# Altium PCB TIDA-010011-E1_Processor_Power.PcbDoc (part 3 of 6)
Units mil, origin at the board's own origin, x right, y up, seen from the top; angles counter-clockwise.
Board outline 4921.26 x 4921.26 mil, 4 copper layers (Top Layer, Gnd layer, Gnd/Pwr layer, Bottom Layer), stack 62.634 mil thick; 631 components, 254 nets, 1751 pads, 757 vias.
Unrouted connection lines stored in the file: 1.
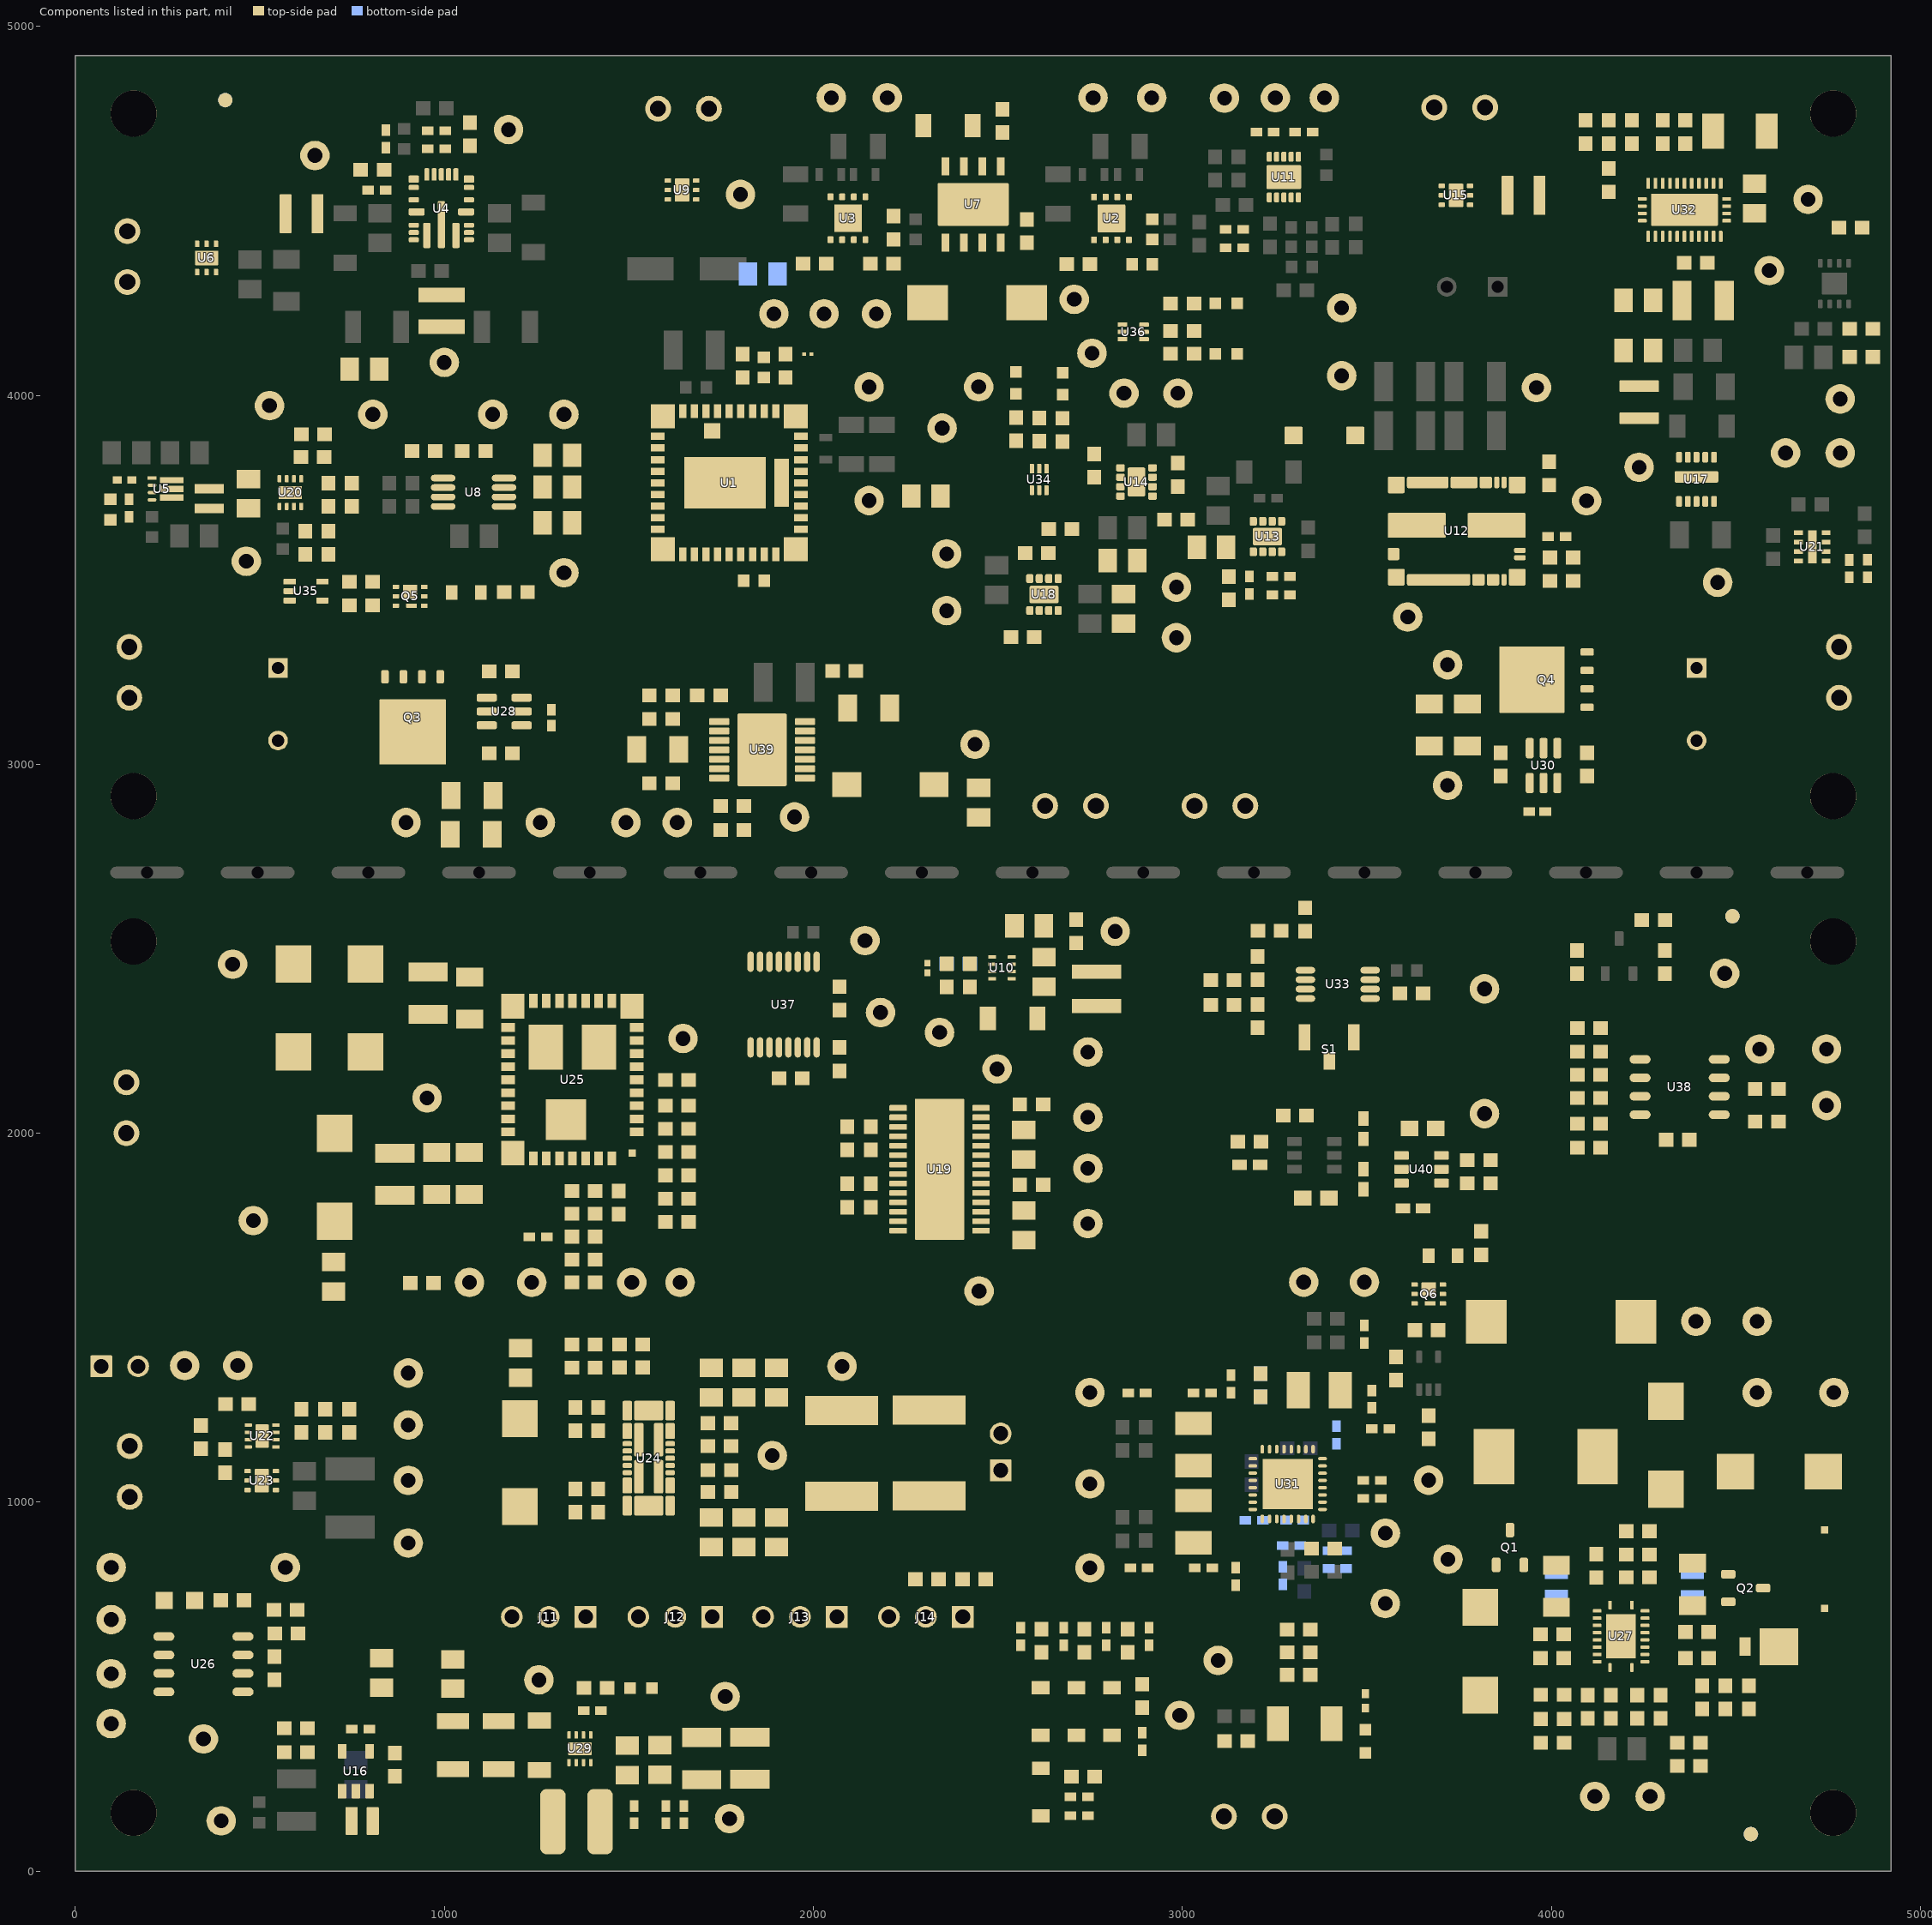
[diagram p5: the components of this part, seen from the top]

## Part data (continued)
C67 C148: "CAP, CERM, 0.1 µF, 25 V,+/- 10%, X7R, 0603", Cap_Case=0603, Manufacturer=MuRata, Supplier Part Number 1=490-1524-1-ND, TempCo=X7R, Tolerance_%=10, Value2=25V, ValueDisplayed=0.1µF
C68 C109 C123: "CAP, CERM, 0.01 µF, 25 V,+/- 10%, X7R, 0603", Cap_Case=0603, Manufacturer=MuRata, Supplier Part Number 1=490-1520-1-ND, TempCo=X7R, Tolerance_%=10, Value2=25V, ValueDisplayed=0.01µF
C69: "CAP, TA, 100 µF, 20 V, +/- 10%, 0.5 ohm, SMD", Cap_Case=E, Manufacturer=Vishay-Sprague, Supplier Part Number 1=718-1024-1-ND, Tolerance_%=10, Value1="0.5 ohm", Value2=20V, ValueDisplayed=100µF
C72 C76 C77 C79 C83 C85 C86: "CAP, CERM, 1 µF, 16 V,+/- 10%, X7R, 0603", Cap_Case=0603, Manufacturer=TDK, Supplier Part Number 1=445-1604-1-ND, TempCo=X7R, Tolerance_%=10, Value1="0.0057 ohm", Value2=16V, ValueDisplayed=1µF
C88 C89 C90 C91: "CAP, CERM, 22 µF, 10 V,+/- 20%, X5R, 0603", Cap_Case=0603, Manufacturer=MuRata, Supplier Part Number 1=490-10476-1-ND, TempCo=X5R, Tolerance_%=20, Value2=10V, ValueDisplayed=22µF
C92 C93 C94 C95 C96 C97 C163: "CAP, CERM, 22 µF, 25 V,+/- 20%, X5R, 0805", Cap_Case=0805, Manufacturer=MuRata, Supplier Part Number 1=490-10749-1-ND, TempCo=X5R, Tolerance_%=20, Value2=25V, ValueDisplayed=22µF
C98 C99: "CAP, CERM, 47 µF, 25 V,+/- 20%, X7S, 6x5x5mm", Cap_Case=2220, Manufacturer=TDK, Supplier Part Number 1=445-7106-1-ND, TempCo=X7S, Tolerance_%=20, Value2=25V, ValueDisplayed=47µF
C100: "CAP, CERM, 3300 pF, 50 V,+/- 10%, X7R, 0603", Cap_Case=0603, Manufacturer=MuRata, Supplier Part Number 1=490-1503-1-ND, TempCo=X7R, Tolerance_%=10, Value2=50V, ValueDisplayed=3300pF
C101 C105: "CAP, Tantalum Polymer, 220 µF, 10 V,+/- 20%, 0.025 ohm, 7343-30 SMD", Cap_Case=7343-30, Manufacturer=Panasonic, Supplier Part Number 1=P16451CT-ND, Tolerance_%=20, Value1="0.025 ohm", Value2=10V, ValueDisplayed=220µF
C102 C103 C108 C162 C164: "CAP, CERM, 0.1 µF, 50 V,+/- 5%, X7R, 1206", Cap_Case=1206, Manufacturer=Kemet, Supplier Part Number 1=399-1250-1-ND, TempCo=X7R, Tolerance_%=5, Value1="0.059 ohm", Value2=50V, ValueDisplayed=0.1µF
C104: "CAP, CERM, 47 µF, 10 V,+/- 10%, X5R, 1210", Cap_Case=1210, Manufacturer=MuRata, Supplier Part Number 1=490-3887-1-ND, TempCo=X5R, Tolerance_%=10, Value1="0.001 ohm", Value2=10V, ValueDisplayed=47µF
C106 C115 C120 C124: "CAP, Tantalum Polymer, 100 µF, 6.3 V,+/- 20%, 0.018 ohm, 7343-20 SMD", Cap_Case=D, Manufacturer=Panasonic, Supplier Part Number 1=P16240CT-ND, Tolerance_%=20, Value1="0.018 ohm", Value2=6.3V, ValueDisplayed=100µF
C107: "CAP, CERM, 47 µF, 6.3 V,+/- 20%, X5R, 1210", Cap_Case=1210, Manufacturer=MuRata, Supplier Part Number 1=490-1887-1-ND, TempCo=X5R, Tolerance_%=20, Value1="0.003 ohm", Value2=6.3V, ValueDisplayed=47µF
C111: "CAP, CERM, 0.022 µF, 16 V,+/- 10%, X7R, 0603", Cap_Case=0603, Manufacturer=Kemet, Supplier Part Number 1=399-1093-1-ND, TempCo=X7R, Tolerance_%=10, Value2=16V, ValueDisplayed=0.022µF
C112 C113 C145 C146 C167: "CAP, CERM, 1 µF, 50 V,+/- 10%, X7R, 0603", Cap_Case=0603, Manufacturer="Taiyo Yuden", Supplier Part Number 1=587-3247-1-ND, TempCo=X7R, Tolerance_%=10, Value2=50V, ValueDisplayed=1µF
C114 C122: "CAP, CERM, 10 µF, 16 V,+/- 10%, X7S, AEC-Q200 Grade 1, 0805", Cap_Case=0805, Manufacturer=TDK, Supplier Part Number 1=445-16110-1-ND, TempCo=X7S, Tolerance_%=10, Value2=16V, ValueDisplayed=10µF
C116 C117: "CAP, CERM, 0.1 µF, 16 V,+80/-20%, Y5V, 0603", Cap_Case=0603, Manufacturer=Kemet, Supplier Part Number 1=399-1098-1-ND, TempCo=Y5V, Tolerance_%=80, Value2=16V, ValueDisplayed=0.1µF
C118 C165: "CAP, CERM, 1 µF, 6.3 V,+/- 10%, X6S, 0603", Cap_Case=0603, Manufacturer=MuRata, Supplier Part Number 1=GRM185C80J105KE26D-ND, TempCo=X6S, Tolerance_%=10, Value2=6.3V, ValueDisplayed=1µF
C119 C121: "CAP, CERM, 1500 pF, 50 V,+/- 10%, X7R, 0603", Cap_Case=0603, Manufacturer=MuRata, Supplier Part Number 1=490-1498-1-ND, TempCo=X7R, Tolerance_%=10, Value2=50V, ValueDisplayed=1500pF
C125: "CAP, CERM, 10 pF, 50 V,+/- 1%, C0G/NP0, 0603", Cap_Case=0603, Manufacturer=Kemet, Supplier Part Number 1=399-9958-1-ND, TempCo=C0G/NP0, Tolerance_%=1, Value2=50V, ValueDisplayed=10pF
C127 C139: "CAP, AL, 680 µF, 25 V, +/- 20%, TH", Cap_Case=10x20, Manufacturer=Chemi-Con, Supplier Part Number 1=565-1679-ND, Tolerance_%=20, Value2=25V, ValueDisplayed=680µF
C128 C140: "CAP, CERM, 1 µF, 50 V, +/- 10%, X5R, 0603", Cap_Case=0603, Manufacturer=MuRata, Supplier Part Number 1=490-10732-1-ND, TempCo=X5R, Tolerance_%=10, Value1=Unknown, Value2=50V, ValueDisplayed=1µF
C129 C141: "CAP, CERM, 1 µF, 50 V, +/- 10%, X7R, 1206", Cap_Case=1206, Manufacturer=TDK, Supplier Part Number 1=445-1423-1-ND, TempCo=X7R, Tolerance_%=10, Value1="0.01 ohm", Value2=50V, ValueDisplayed=1µF
C130 C142: "CAP, CERM, 0.1 µF, 50 V, +/- 5%, X7R, 1206", Cap_Case=1206, Manufacturer=Kemet, Supplier Part Number 1=399-1250-1-ND, TempCo=X7R, Tolerance_%=5, Value1="0.059 ohm", Value2=50V, ValueDisplayed=0.1µF
C131 C132: library part CMP-0009116-1, "CAP, CERM, 22 uF, 16 V, +/- 10%, X7R, 1210", Cap_Case=1210_280, Manufacturer=TDK, Supplier Part Number 1=445-3945-1-ND, TempCo=X7R, Tolerance_%=10%, Value1="0.002582 ohm", Value2=16V, ValueDisplayed=22uF
C133: library part CMP-0008692-2, "CAP, CERM, 10 uF, 25 V, +/- 20%, X7R, 1206_190", Cap_Case=1206, Manufacturer=TDK, Supplier Part Number 1=445-6812-1-ND, TempCo=X7R, Tolerance_%=20%, Value1=Unknown, Value2=25V, ValueDisplayed=10uF
C134 C135: library part CMP-0007890-2, "CAP, CERM, 22 uF, 10 V, +/- 20%, X7S, 0805", Cap_Case=0805, Manufacturer=TDK, Supplier Part Number 1=445-14560-1-ND, TempCo=X7S, Tolerance_%=20%, Value1="0.00205 ohm", Value2=10V, ValueDisplayed=22uF
C136 C137: library part CMP-0009220-2, "CAP, CERM, 47 uF, 10 V, +/- 10%, X7R, 1210", Cap_Case=1210, Manufacturer=MuRata, Supplier Part Number 1=490-5312-1-ND, TempCo=X7R, Tolerance_%=10%, Value1=Unknown, Value2=10V, ValueDisplayed=47uF
C138: library part CMP-0006348-2, "CAP, CERM, 22 pF, 50 V, +/- 5%, C0G/NP0, AEC-Q200 Grade 1, 0402", Cap_Case=0402, Manufacturer=MuRata, Supplier Part Number 1=490-9648-1-ND, TempCo=C0G/NP0, Tolerance_%=5%, Value1=Unknown, Value2=50V, ValueDisplayed=22pF
C143 C144: "CAP, CERM, 33 µF, 10 V,+/- 20%, X5R, 0805", Cap_Case=0805, Manufacturer=TDK, Supplier Part Number 1=445-8238-1-ND, TempCo=X5R, Tolerance_%=20, Value1="0.001694 ohm", Value2=10V, ValueDisplayed=33µF
C149 C151: "CAP, CERM, 0.47 µF, 50 V,+/- 10%, X7R, 0603", Cap_Case=0603, Manufacturer=TDK, Supplier Part Number 1=445-5952-1-ND, TempCo=X7R, Tolerance_%=10, Value1="0.010974 ohm", Value2=50V, ValueDisplayed=0.47µF
C150: "CAP, CERM, 10 µF, 50 V,+/- 10%, X7R, 1210", Cap_Case=1210, Manufacturer=MuRata, Supplier Part Number 1=490-6544-1-ND, TempCo=X7R, Tolerance_%=10, Value2=50V, ValueDisplayed=10µF
C152: "CAP, CERM, 2.2 µF, 10 V,+/- 20%, X5R, 0603", Cap_Case=0603, Manufacturer=Kemet, Supplier Part Number 1=399-4912-1-ND, TempCo=X5R, Tolerance_%=20, Value2=10V, ValueDisplayed=2.2µF
C153: "CAP, CERM, 47 µF, 10 V,+/- 20%, X5R, 0805", Cap_Case=0805, Manufacturer=MuRata, Supplier Part Number 1=490-9961-1-ND, TempCo=X5R, Tolerance_%=20, Value2=10V, ValueDisplayed=47µF
C154: "CAP, CERM, 47 pF, 50 V,+/- 5%, C0G/NP0, AEC-Q200 Grade 1, 0603", Cap_Case=0603, Manufacturer=TDK, Supplier Part Number 1=445-5636-1-ND, TempCo=C0G/NP0, Tolerance_%=5, Value2=50V, ValueDisplayed=47pF
C156 C158 C175 C182: "CAP, CERM, 0.1 µF, 25 V,+/- 10%, X5R, 0603", Cap_Case=0603, Manufacturer=AVX, Supplier Part Number 1=478-1244-1-ND, TempCo=X5R, Tolerance_%=10, Value1="0.048 ohm", Value2=25V, ValueDisplayed=0.1µF
C157 C193: library part 06033C104JAT2A, "0.1µF ±10% 35V Ceramic Capacitor X5R 0603", Cap_Case=0603, Manufacturer="Taiyo Yuden", Supplier Part Number 1=587-3357-1-ND, TempCo=X7R, Tolerance_%=5, Value1="0.05 ohm", Value2=25V, ValueDisplayed=0.1µF
C160 C189 C190: "CAP, CERM, 0.1 µF, 25 V,+/- 10%, X7R, 0603", Cap_Case=0603, Manufacturer=AVX, Supplier Part Number 1=478-3714-1-ND, TempCo=X7R, Tolerance_%=10, Value1="0.05 ohm", Value2=25V, ValueDisplayed=0.1µF
C166 C168: "CAP, CERM, 0.1uF, 25V, +/-5%, X7R, 0603", Cap_Case=0603, Manufacturer=AVX, Supplier Part Number 1=478-3713-1-ND, TempCo=X7R, Tolerance_%=5, Value1="0.05 ohm", Value2=25V, ValueDisplayed=0.1µF
C169: "CAP, CERM, 150 pF, 50 V, +/- 5%, C0G/NP0, 0603", Cap_Case=0603, Manufacturer=AVX, Supplier Part Number 1=478-1177-1-ND, TempCo=C0G/NP0, Tolerance_%=5, Value1="0.098 ohm", Value2=50V, ValueDisplayed=150pF
C173: "CAP, CERM, 0.01 µF, 10 V,+/- 10%, X7R, 0603", Cap_Case=0603, Manufacturer=AVX, Supplier Part Number 1=478-7938-2-ND, TempCo=X7R, Tolerance_%=10, Value2=10V, ValueDisplayed=0.01µF
C174: "CAP, CERM, 22 µF, 10 V,+/- 10%, X7R, 1206", Cap_Case=1206, Manufacturer=MuRata, Supplier Part Number 1=490-5309-1-ND, TempCo=X7R, Tolerance_%=10, Value2=10V, ValueDisplayed=22µF
C176: "CAP, Aluminum Polymer, 330 µF, 2 V,+/- 20%, 0.003 ohm, SMD_7.3x1.9x4.3mm SMD", Cap_Case=D, Manufacturer=Panasonic, Supplier Part Number 1=PCE5027CT-ND, Tolerance_%=20, Value1="0.003 ohm", Value2=2V, ValueDisplayed=330µF
C178 C181: "CAP, CERM, 0.1 µF, 16 V, +/- 10%, X7R, 0603", Cap_Case=0603, Manufacturer=MuRata, Supplier Part Number 1=490-1532-1-ND, TempCo=X7R, Tolerance_%=10, Value1=Unknown, Value2=16V, ValueDisplayed=0.1µF
C179 C180: "CAP, CERM, 22 µF, 10 V, +/- 20%, X5R, 0603", Cap_Case=0603, Manufacturer=MuRata, Supplier Part Number 1=490-10476-1-ND, TempCo=X5R, Tolerance_%=20, Value1=Unknown, Value2=10V, ValueDisplayed=22µF
C183: library part CMP-0009765-1, "CAP, CERM, 120 pF, 25 V, +/- 10%, X7R, 0201", Cap_Case=0201, Manufacturer=MuRata, Supplier Part Number 1=490-3173-1-ND, TempCo=X7R, Tolerance_%=10%, Value1=Unknown, Value2=25V, ValueDisplayed=120pF
C184: "CAP, CERM, 4.7 µF, 35 V, +/- 10%, X7R, 0805", Cap_Case=0805, Manufacturer=TDK, Supplier Part Number 1=445-7555-1-ND, TempCo=X7R, Tolerance_%=10, Value1="0.002346 ohm", Value2=35V, ValueDisplayed=4.7µF
C185: library part CMP-0008805-2, "CAP, CERM, 22 uF, 16 V, +/- 20%, X7R, 1206_190", Cap_Case=1206, Manufacturer="Taiyo Yuden", Supplier Part Number 1=587-4319-1-ND, TempCo=X7R, Tolerance_%=20%, Value1=Unknown, Value2=16V, ValueDisplayed=22uF
C186: "CAP, CERM, 4.7 µF, 6.3 V,+/- 20%, X5R, 0402", Cap_Case=0402, Manufacturer=MuRata, Supplier Part Number 1=490-5915-1-ND, TempCo=X5R, Tolerance_%=20, Value2=6.3V, ValueDisplayed=4.7µF
CVCC1: "CAP, CERM, 4.7 µF, 10 V,+/- 10%, X5R, 0603", Cap_Case=0603, Manufacturer=TDK, Supplier Part Number 1=445-7482-1-ND, TempCo=X5R, Tolerance_%=10, Value2=10V, ValueDisplayed=4.7µF
D1: "Diode, Schottky, 20 V, 3 A, SMC", Manufacturer=Vishay-Semiconductor, Supplier Part Number 1=SS32-E3/57TGICT-ND, Value1=3A, Value2=0.5V
D2: "Diode, Schottky, 20 V, 1 A, POWERMITE", Manufacturer="ON Semiconductor", Supplier Part Number 1=MBRM120ET1GOSCT-ND, Value1=1A, Value2=0.53V
D3 D4: "Diode, Zener, 4.7 V, 300 mW, SOD-523", Manufacturer="Diodes Inc.", Power_W=0.3, Supplier Part Number 1=BZT52C4V7T-7DICT-ND, Value1=0.3W
D5: "LED, Red, SMD", Color=red, Manufacturer=Lite-On, PartNumber=LTST-C170KRKT, Supplier Part Number 1=160-1415-1-ND, Value1=W, Value2=2V
D6 D7 D8 D10 D16: "LED, Green, SMD", Color=green, Manufacturer=Lite-On, Supplier Part Number 1=160-1435-1-ND, Value1=W, Value2=2V
D9 D17: "LED, Green, SMD", Color=Green, Manufacturer=OSRAM, Supplier Part Number 1=475-1406-1-ND, Value1=W, Value2=1.8V
D11 D12 D13 D14: "Diode, Schottky, 40 V, 0.5 A, SOD-123", Manufacturer="ON Semiconductor", Supplier Part Number 1=MBR0540T1GOSCT-ND, Value1=0.5A, Value2=0.51V
D15: "LED, Green, SMD", Color=green, Manufacturer="Wurth Elektronik", Supplier Part Number 1=732-4980-1-ND, Value1=W, Value2=2V
FID1 FID2 FID3 FID4 FID5 FID6: "Fiducial mark.  There is nothing to buy or mount.", Manufacturer=N/A
H1 H2 H3 H4 H5 H6 H7 H8: library part "PMSSS 440 0025 PH", "MACHINE SCREW PAN PHILLIPS 4-40", Manufacturer="Essentra Components", Supplier Part Number 1=RPC1579-ND
H9 H10 H11 H12 H13 H14 H15 H16: "Standoff, Hex, 1\"L #4-40 Nylon", Manufacturer=Keystone, Supplier Part Number 1=36-1902E-ND
J1 J2 J3 J4 J5 J16 J18 J19 J20 J21: "Conn Term Block, 2POS, 3.5mm, TH", Manufacturer="Phoenix Contact", Supplier Part Number 1=277-5719-ND
J6 J10: "Header, 100mil, 2x1, Tin, TH", Color=Black, Current_A=3, Manufacturer="Sullins Connector Solutions", Supplier Part Number 1=S1012E-02-ND, Voltage_V=1800
J11 J12 J13 J14: "Header, 100mil, 3x1, Tin, TH", Color=Black, Current_A=3, Manufacturer="Sullins Connector Solutions", Supplier Part Number 1=S1012E-03-ND, Voltage_V=1800
L1 L4 L6: "Inductor, Wirewound, Ferrite, 3.3 µH, 1.21 A, 0.096 ohm, AEC-Q200 Grade 2, SMD", Manufacturer="Taiyo Yuden", Supplier Part Number 1=587-2619-1-ND, Value1="0.096 ohm", Value2=1.21A, ValueDisplayed=3.3µH
L2: "Inductor, Shielded Drum Core, Ferrite, 6.8 µH, 1.1 A, 0.142 ohm, SMD", Manufacturer="Wurth Elektronik", Supplier Part Number 1=732-2616-1-ND, Value1="0.142 ohm", Value2=1.1A, ValueDisplayed=6.8µH
L3: "Inductor, Shielded Drum Core, Ferrite, 470 nH, 2 A, 0.059 ohm, SMD", Manufacturer=TDK, Supplier Part Number 1=445-6606-1-ND, Value1="0.059 ohm", Value2=2A, ValueDisplayed=470nH
L5: "Ferrite Bead, 1000 ohm @ 100 MHz, 1.5 A, 1806", Manufacturer=MuRata, Supplier Part Number 1=490-1061-1-ND, Value1="0.09 ohm", Value2=1.5A, ValueDisplayed="1000 ohm"
L7 L17: "Ferrite Bead, 600 ohm @ 100MHz, 2A, 0805", Manufacturer=TDK, Supplier Part Number 1=445-2206-1-ND, Value1="0.1 ohm", Value2=2A
L8: "Inductor, Drum Core, Ferrite, 15uH, 2.9A, 0.0432 ohm, SMD", Manufacturer="Wurth Elektronik eiSos", Supplier Part Number 1=732-1351-1-ND, Value1="0.0432 ohm", Value2=2.9A, ValueDisplayed=15µH
L9: "Inductor, Shielded Drum Core, Ferrite, 5uH, 1.65A, 0.047 ohm, SMD", Manufacturer="Wurth Elektronik eiSos", Supplier Part Number 1=732-1031-1-ND, Value1="0.047 ohm", Value2=1.65A, ValueDisplayed=5µH
L10: "Inductor, Shielded Drum Core, Ferrite, 1 µH, 4 A, 0.049 ohm, SMD", Manufacturer="Wurth Elektronik", Supplier Part Number 1=732-1249-1-ND, Value1="0.049 ohm", Value2=4A, ValueDisplayed=1µH
L11: "Inductor, Shielded Drum Core, Powdered Iron, 1.5uH, 3.8A, 0.0348 ohm, SMD", Manufacturer="Wurth Elektronik eiSos", Supplier Part Number 1=732-3346-1-ND, Value1="0.0348 ohm", Value2=3.8A, ValueDisplayed=1.5µH
L12 L13: "Inductor, Shielded, Ferrite, 2.2 µH, 1.72 A, 0.059 ohm, SMD", Manufacturer=TDK, Supplier Part Number 1=445-3182-1-ND, Value1="0.059 ohm", Value2=1.72A, ValueDisplayed=2.2µH
L14: "Inductor, Shielded, Ferrite, 3.3 µH, 1.52 A, 0.078 ohm, SMD", Manufacturer=TDK, Supplier Part Number 1=445-3183-1-ND, Value1="0.078 ohm", Value2=1.52A, ValueDisplayed=3.3µH
L15: "Inductor, Shielded Drum Core, Powdered Iron, 1uH, 5A, 0.022 ohm, SMD", Manufacturer="Wurth Elektronik eiSos", Supplier Part Number 1=732-3342-1-ND, Value1="0.022 ohm", Value2=5A, ValueDisplayed=1µH
L16: library part CMP-0064289-1, "Inductor, Shielded Drum Core, Ferrite, 2.2 uH, 4.02 A, 0.019 ohm, SMD", Manufacturer="Wurth Elektronik", Supplier Part Number 1=732-1173-1-ND, Value1="0.019 ohm", Value2=4.02A, ValueDisplayed=2.2uH
L18: library part CMP-0061147-1, "Inductor, Shielded, Composite, 470 nH, 3.5 A, 0.0076 ohm, SMD", Manufacturer=Coilcraft, Supplier Part Number 1=994-XFL4015-471MEC, Value1="0.0076 ohm", Value2=3.5A, ValueDisplayed=470nH
L19: "Inductor, Shielded, 2.2 µH, 1.1 A, 0.27 ohm, SMD", Manufacturer="Wurth Elektronik", Supplier Part Number 1=732-5709-1-ND, Value1="0.27 ohm", Value2=1.1A, ValueDisplayed=2.2µH
LBL1: library part THT-14-423-10, "Thermal Transfer Printable Labels, 0.650\" W x 0.200\" H - 10,000 per roll", Alternate Manufacturer=-, Manufacturer=Brady, Supplier Part Number 1=2065596
Logo2: library part Pb-Free
Logo3: library part FCC_disclaimer, "FCC_disclaimer"
Logo4: library part ESD_Susceptible, "ESD Susceptible Symbol"
NT1: "Single point connection between nets."
Q1 Q2: library part CMP-0000092-2, "MOSFET, P-CH, -20 V, -3.7 A, SOT-23", Alternate Manufacturer=None, Manufacturer=Vishay-Siliconix, Supplier Part Number 1=SI2323DS-T1-E3CT-ND, Value1=0.03, Value2="12.5 nC"
Q3 Q4: library part CMP-0000708-1, "MOSFET, N-CH, 40 V, 15 A, DQJ0008A (VSONP-8)", Alternate Manufacturer=None, Manufacturer="Texas Instruments", Supplier Part Number 1=296-30572-1-ND, Value1=0.009, Value2="7.7 nC"
Q5 Q6: "MOSFET, N-CH, 30 V, 22 A, DQK0006C (WSON-6)", Alternate Manufacturer=None, Manufacturer="Texas Instruments", Supplier Part Number 1=296-37193-1-ND, Value1="0.029 ohm", Value2="2.4 nC"
R1: "RES, 80.6 k, 1%, 0.1 W, 0603", Manufacturer=Vishay-Dale, Power_W=0.1, Supplier Part Number 1=541-80.6KHCT-ND, TempCo="100 ppm/C", Tolerance_%=1, Value1=1%, Value2=0.1W, Value_Code=80k6, ValueDisplayed=80.6k
R2: "RES, 40.2 k, 1%, 0.1 W, 0603", Manufacturer=Vishay-Dale, Power_W=0.1, Supplier Part Number 1=541-40.2KHCT-ND, TempCo="100 ppm/C", Tolerance_%=1, Value1=1%, Value2=0.1W, Value_Code=40k2, ValueDisplayed=40.2k
R3: "RES, 97.6 k, 1%, 0.1 W, 0603", Manufacturer=Vishay-Dale, Power_W=0.1, Supplier Part Number 1=541-97.6KHCT-ND, TempCo="100 ppm/C", Tolerance_%=1, Value1=1%, Value2=0.1W, Value_Code=97k6, ValueDisplayed=97.6k
R4: "RES, 8.87 k, 1%, 0.1 W, 0603", Manufacturer=Vishay-Dale, Power_W=0.1, Supplier Part Number 1=541-8.87KHCT-ND, TempCo="100 ppm/C", Tolerance_%=1, Value1=1%, Value2=0.1W, Value_Code=8k87, ValueDisplayed=8.87k
R5 R45: "RES, 240 k, 1%, 0.1 W, 0603", Manufacturer="Yageo America", Power_W=0.1, Supplier Part Number 1=311-240KHRCT-ND, TempCo="200 ppm/C", Tolerance_%=1, Value1=1%, Value2=0.1W, Value_Code=240k
R6: "RES, 53.6 k, 1%, 0.1 W, 0603", Manufacturer="Yageo America", Power_W=0.1, Supplier Part Number 1=311-53.6KHRCT-ND, TempCo="200 ppm/C", Tolerance_%=1, Value1=1%, Value2=0.1W, Value_Code=53k6, ValueDisplayed=53.6k
R7: "RES, 487 k, 1%, 0.063 W, 0402", Manufacturer=Vishay-Dale, Power_W=0.063, Supplier Part Number 1=541-487KLCT-ND, TempCo="100 ppm/C", Tolerance_%=1, Value1=1%, Value2=0.063W, Value_Code=487k
R8: "RES, 1.00 M, 1%, 0.063 W, 0402", Manufacturer="Yageo America", Power_W=0.063, Supplier Part Number 1=311-1.00MLRCT-ND, TempCo="100 ppm/C", Tolerance_%=1, Value1=1%, Value2=0.063W, Value_Code=1M00, ValueDisplayed=1.00M
R9: "RES, 22.6 k, 1%, 0.063 W, 0402", Manufacturer=Vishay-Dale, Power_W=0.063, Supplier Part Number 1=541-22.6KLCT-ND, TempCo="100 ppm/C", Tolerance_%=1, Value1=1%, Value2=0.063W, Value_Code=22k6, ValueDisplayed=22.6k
R10 R17 R26 R54: "RES, 100 k, 1%, 0.063 W, 0402", Manufacturer=Vishay-Dale, Power_W=0.063, Supplier Part Number 1=541-100KLCT-ND, TempCo="100 ppm/C", Tolerance_%=1, Value1=1%, Value2=0.063W, Value_Code=100k
R11 R30 R37: "RES, 162 k, 1%, 0.1 W, 0603", Manufacturer="Yageo America", Power_W=0.1, Supplier Part Number 1=311-162KHRCT-ND, TempCo="200 ppm/C", Tolerance_%=1, Value1=1%, Value2=0.1W, Value_Code=162k
R12 R13 R14: "RES, 100 k, 1%, 0.125 W, 0805", Manufacturer=Panasonic, Power_W=0.125, Supplier Part Number 1=P100KCCT-ND, TempCo="100 ppm/C", Tolerance_%=1, Value1=1%, Value2=0.125W, Value_Code=100k
R15 R16: "RES, 1.0 k, 5%, 0.1 W, 0603", Manufacturer=Vishay-Dale, Power_W=0.1, Supplier Part Number 1=541-1.0KGCT-ND, TempCo="200 ppm/C", Tolerance_%=5, Value1=5%, Value2=0.1W, Value_Code=1k00, ValueDisplayed=1.0k
R18: "RES, 5.11 k, 1%, 0.1 W, 0603", Manufacturer="Yageo America", Power_W=0.1, Supplier Part Number 1=311-5.11KHRCT-ND, TempCo="200 ppm/C", Tolerance_%=1, Value1=1%, Value2=0.1W, Value_Code=5k11, ValueDisplayed=5.11k
R19 R22 R24: "RES, 10.0 k, 1%, 0.063 W, 0402", Manufacturer=Vishay-Dale, Power_W=0.063, Supplier Part Number 1=541-10.0KLCT-ND, TempCo="100 ppm/C", Tolerance_%=1, Value1=1%, Value2=0.063W, Value_Code=10k0, ValueDisplayed=10.0k
R20 R38 R56 R57 R67 R74 R103 R106: "RES, 100 k, 1%, 0.1 W, 0603", Manufacturer="Yageo America", Power_W=0.1, Supplier Part Number 1=311-100KHRCT-ND, TempCo="200 ppm/C", Tolerance_%=1, Value1=1%, Value2=0.1W, Value_Code=100k
R21 R23: "RES, 10 k, 5%, 0.063 W, 0402", Manufacturer=Vishay-Dale, Power_W=0.063, Supplier Part Number 1=541-10KJCT-ND, TempCo="200 ppm/C", Tolerance_%=5, Value1=5%, Value2=0.063W, Value_Code=10k0, ValueDisplayed=10k
R25: "RES, 80.6 k, 1%, 0.1 W, 0603", Manufacturer="Yageo America", Power_W=0.1, Supplier Part Number 1=311-80.6KHRCT-ND, TempCo="200 ppm/C", Tolerance_%=1, Value1=1%, Value2=0.1W, Value_Code=80k6, ValueDisplayed=80.6k
R27: "RES, 34.8 k, 1%, 0.1 W, 0603", Manufacturer=Vishay-Dale, Power_W=0.1, Supplier Part Number 1=541-34.8KHCT-ND, TempCo="100 ppm/C", Tolerance_%=1, Value1=1%, Value2=0.1W, Value_Code=34k8, ValueDisplayed=34.8k
R28: "RES, 59.0 k, 1%, 0.063 W, 0402", Manufacturer=Vishay-Dale, Power_W=0.063, Supplier Part Number 1=541-59.0KLCT-ND, TempCo="100 ppm/C", Tolerance_%=1, Value1=1%, Value2=0.063W, Value_Code=59k0, ValueDisplayed=59.0k
R29 R36: "RES, 499 k, 1%, 0.1 W, AEC-Q200 Grade 0, 0603", Manufacturer=Panasonic, Power_W=0.1, Supplier Part Number 1=P499KHCT-ND, TempCo="100 ppm/C", Tolerance_%=1, Value1=1%, Value2=0.1W, Value_Code=499k
R31: "RES, 11.3 k, 1%, 0.063 W, 0402", Manufacturer=Vishay-Dale, Power_W=0.063, Supplier Part Number 1=541-11.3KLCT-ND, TempCo="100 ppm/C", Tolerance_%=1, Value1=1%, Value2=0.063W, Value_Code=11k3, ValueDisplayed=11.3k
R32: "RES, 110 k, 1%, 0.1 W, 0603", Manufacturer="Yageo America", Power_W=0.1, Supplier Part Number 1=311-110KHRCT-ND, TempCo="200 ppm/C", Tolerance_%=1, Value1=1%, Value2=0.1W, Value_Code=110k
R33 R34: "RES, 44.2 k, 1%, 0.1 W, 0603", Manufacturer=Vishay-Dale, Power_W=0.1, Supplier Part Number 1=541-44.2KHCT-ND, TempCo="100 ppm/C", Tolerance_%=1, Value1=1%, Value2=0.1W, Value_Code=44k2, ValueDisplayed=44.2k
R35: "RES, 200 k, 1%, 0.1 W, 0603", Manufacturer="Yageo America", Power_W=0.1, Supplier Part Number 1=311-200KHRCT-ND, TempCo="200 ppm/C", Tolerance_%=1, Value1=1%, Value2=0.1W, Value_Code=200k
R39: "RES, 118 k, 1%, 0.063 W, 0402", Manufacturer=Vishay-Dale, Power_W=0.063, Supplier Part Number 1=541-118KLCT-ND, TempCo="100 ppm/C", Tolerance_%=1, Value1=1%, Value2=0.063W, Value_Code=118k
R40: "RES, 150 k, 1%, 0.063 W, 0402", Manufacturer=Vishay-Dale, Power_W=0.063, Supplier Part Number 1=541-150KLCT-ND, TempCo="100 ppm/C", Tolerance_%=1, Value1=1%, Value2=0.063W, Value_Code=150k
R41: "RES, 1.00 M, 1%, 0.1 W, 0603", Manufacturer=Vishay-Dale, Power_W=0.1, Supplier Part Number 1=541-1.00MHCT-ND, TempCo="100 ppm/C", Tolerance_%=1, Value1=1%, Value2=0.1W, Value_Code=1M00, ValueDisplayed=1.00M
R42: "RES, 487, 1%, 0.1 W, 0603", Manufacturer=Vishay-Dale, Power_W=0.1, Supplier Part Number 1=541-487HCT-ND, TempCo="100 ppm/C", Tolerance_%=1, Value1=1%, Value2=0.1W, Value_Code=487R, ValueDisplayed=487
R43: "RES, 1.02 k, 1%, 0.1 W, 0603", Manufacturer="Yageo America", Power_W=0.1, Supplier Part Number 1=311-1.02KHRCT-ND, TempCo="200 ppm/C", Tolerance_%=1, Value1=1%, Value2=0.1W, Value_Code=1k02, ValueDisplayed=1.02k
R44: "RES, 4.42 k, 1%, 0.1 W, 0603", Manufacturer=Vishay-Dale, Power_W=0.1, Supplier Part Number 1=541-4.42KHCT-ND, TempCo="100 ppm/C", Tolerance_%=1, Value1=1%, Value2=0.1W, Value_Code=4k42, ValueDisplayed=4.42k
R46 R47 R50 R51: "RES, 470 k, 1%, 0.1 W, 0603", Manufacturer="Yageo America", Power_W=0.1, Supplier Part Number 1=311-470KHRCT-ND, TempCo="200 ppm/C", Tolerance_%=1, Value1=1%, Value2=0.1W, Value_Code=470k
R48: "RES, 205 k, 1%, 0.1 W, 0603", Manufacturer=Vishay-Dale, Power_W=0.1, Supplier Part Number 1=541-205KHCT-ND, TempCo="100 ppm/C", Tolerance_%=1, Value1=1%, Value2=0.1W, Value_Code=205k
R49: "RES, 120 k, 1%, 0.1 W, 0603", Manufacturer="Yageo America", Power_W=0.1, Supplier Part Number 1=311-120KHRCT-ND, TempCo="200 ppm/C", Tolerance_%=1, Value1=1%, Value2=0.1W, Value_Code=120k
R52 R53: "RES, 1.00 k, 1%, 0.1 W, 0603", Manufacturer="Yageo America", Power_W=0.1, Supplier Part Number 1=311-1.00KHRCT-ND, TempCo="200 ppm/C", Tolerance_%=1, Value1=1%, Value2=0.1W, Value_Code=1k00, ValueDisplayed=1.00k
R55 R71 R72 R73 R75 R104 R105 R143 R144 R145 R154 R159: "RES, 0, 5%, 0.1 W, 0603", Manufacturer=Panasonic, Power_W=0.1, Supplier Part Number 1=P0.0GCT-ND, TempCo="600 ppm/C", Tolerance_%=5, Value1=5%, Value2=0.1W, Value_Code=0000, ValueDisplayed=0
R58: "RES, 2.87 k, 1%, 0.1 W, 0603", Manufacturer=Vishay-Dale, Power_W=0.1, Supplier Part Number 1=541-2.87KHCT-ND, TempCo="100 ppm/C", Tolerance_%=1, Value1=1%, Value2=0.1W, Value_Code=2k87, ValueDisplayed=2.87k
R59: "RES, 1.15 k, 1%, 0.1 W, 0603", Manufacturer=Vishay-Dale, Power_W=0.1, Supplier Part Number 1=541-1.15KHCT-ND, TempCo="100 ppm/C", Tolerance_%=1, Value1=1%, Value2=0.1W, Value_Code=1k15, ValueDisplayed=1.15k
R60: "RES, 681, 1%, 0.1 W, 0603", Manufacturer=Vishay-Dale, Power_W=0.1, Supplier Part Number 1=541-681HCT-ND, TempCo="100 ppm/C", Tolerance_%=1, Value1=1%, Value2=0.1W, Value_Code=681R, ValueDisplayed=681
R61: "RES, 464, 1%, 0.1 W, 0603", Manufacturer=Vishay-Dale, Power_W=0.1, Supplier Part Number 1=541-464HCT-ND, TempCo="100 ppm/C", Tolerance_%=1, Value1=1%, Value2=0.1W, Value_Code=464R, ValueDisplayed=464
R62: "RES, 113 k, 1%, 0.1 W, 0603", Manufacturer=Vishay-Dale, Power_W=0.1, Supplier Part Number 1=541-113KHCT-ND, TempCo="100 ppm/C", Tolerance_%=1, Value1=1%, Value2=0.1W, Value_Code=113k
R63: "RES, 174 k, 1%, 0.1 W, 0603", Manufacturer=Vishay-Dale, Power_W=0.1, Supplier Part Number 1=541-174KHCT-ND, TempCo="100 ppm/C", Tolerance_%=1, Value1=1%, Value2=0.1W, Value_Code=174k
R64: "RES, 348 k, 1%, 0.1 W, 0603", Manufacturer=Vishay-Dale, Power_W=0.1, Supplier Part Number 1=541-348KHCT-ND, TempCo="100 ppm/C", Tolerance_%=1, Value1=1%, Value2=0.1W, Value_Code=348k
R65: "RES, 715 k, 1%, 0.1 W, 0603", Manufacturer=Vishay-Dale, Power_W=0.1, Supplier Part Number 1=541-715KHCT-ND, TempCo="100 ppm/C", Tolerance_%=1, Value1=1%, Value2=0.1W, Value_Code=715k
R66: "RES, 1.21 M, 1%, 0.1 W, 0603", Manufacturer=Vishay-Dale, Power_W=0.1, Supplier Part Number 1=541-1.21MHCT-ND, TempCo="100 ppm/C", Tolerance_%=1, Value1=1%, Value2=0.1W, Value_Code=1M21, ValueDisplayed=1.21M
R68: "RES, 360 k, 1%, 0.063 W, AEC-Q200 Grade 0, 0402", Manufacturer=Vishay-Dale, Power_W=0.063, Supplier Part Number 1=541-360KLCT-ND, TempCo="100 ppm/C", Tolerance_%=1, Value1=1%, Value2=0.063W, Value_Code=360k
R69: "RES, 182 k, 1%, 0.063 W, 0402", Manufacturer=Vishay-Dale, Power_W=0.063, Supplier Part Number 1=541-182KLCT-ND, TempCo="100 ppm/C", Tolerance_%=1, Value1=1%, Value2=0.063W, Value_Code=182k
R70 R76: "RES, 0.033, 1%, 1 W, AEC-Q200 Grade 0, 1206", Manufacturer=Panasonic, Power_W=1, Supplier Part Number 1=P0.033BVCT-ND, TempCo="50 ppm/C", Value1=1%, Value2=1W, Value_Code=R033, ValueDisplayed=0.033
R77 R81 R83 R84 R89 R93 R94 R98 R102: "RES, 0, 5%, 0.063 W, 0402", Manufacturer=Vishay-Dale, Power_W=0.063, Supplier Part Number 1=541-0.0JCT-ND, TempCo="200 ppm/C", Tolerance_%=5, Value1=5%, Value2=0.063W, Value_Code=0000, ValueDisplayed=0
R78: "RES, 165 k, 1%, 0.063 W, 0402", Manufacturer=Vishay-Dale, Power_W=0.063, Supplier Part Number 1=541-165KLCT-ND, TempCo="100 ppm/C", Tolerance_%=1, Value1=1%, Value2=0.063W, Value_Code=165k
R79 R86 R97 R100: "RES, 200 k, 1%, 0.063 W, 0402", Manufacturer=Vishay-Dale, Power_W=0.063, Supplier Part Number 1=541-200KLCT-ND, TempCo="100 ppm/C", Tolerance_%=1, Value1=1%, Value2=0.063W, Value_Code=200k
R80: "RES, 2.0, 5%, 0.1 W, 0603", Manufacturer=Vishay-Dale, Power_W=0.1, Supplier Part Number 1=541-2.0GCT-ND, TempCo="200 ppm/C", Tolerance_%=5, Value1=5%, Value2=0.1W, Value_Code=2R00, ValueDisplayed=2.0
R82: "RES, 301 k, 1%, 0.063 W, 0402", Manufacturer=Vishay-Dale, Power_W=0.063, Supplier Part Number 1=541-301KLCT-ND, TempCo="100 ppm/C", Tolerance_%=1, Value1=1%, Value2=0.063W, Value_Code=301k
R85: "RES, 4.99 k, 1%, 0.063 W, 0402", Manufacturer=Vishay-Dale, Power_W=0.063, Supplier Part Number 1=541-4.99KLCT-ND, TempCo="100 ppm/C", Tolerance_%=1, Value1=1%, Value2=0.063W, Value_Code=4k99, ValueDisplayed=4.99k
R87 R91: "RES, 2.00 k, 1%, 0.063 W, 0402", Manufacturer=Vishay-Dale, Power_W=0.063, Supplier Part Number 1=541-2.00KLCT-ND, TempCo="100 ppm/C", Tolerance_%=1, Value1=1%, Value2=0.063W, Value_Code=2k00, ValueDisplayed=2.00k
R88 R95: "RES, 1.00 k, 1%, 0.063 W, 0402", Manufacturer=Vishay-Dale, Power_W=0.063, Supplier Part Number 1=541-1.00KLCT-ND, TempCo="100 ppm/C", Tolerance_%=1, Value1=1%, Value2=0.063W, Value_Code=1k00, ValueDisplayed=1.00k
R90: "RES, 432 k, 1%, 0.063 W, 0402", Manufacturer=Vishay-Dale, Power_W=0.063, Supplier Part Number 1=541-432KLCT-ND, TempCo="100 ppm/C", Tolerance_%=1, Value1=1%, Value2=0.063W, Value_Code=432k
R92: "RES, 95.3 k, 1%, 0.063 W, 0402", Manufacturer=Vishay-Dale, Power_W=0.063, Supplier Part Number 1=541-95.3KLCT-ND, TempCo="100 ppm/C", Tolerance_%=1, Value1=1%, Value2=0.063W, Value_Code=95k3, ValueDisplayed=95.3k
R96 R99: "RES, 162 k, 1%, 0.063 W, 0402", Manufacturer=Vishay-Dale, Power_W=0.063, Supplier Part Number 1=541-162KLCT-ND, TempCo="100 ppm/C", Tolerance_%=1, Value1=1%, Value2=0.063W, Value_Code=162k
R101: "RES, 100 k, 5%, 0.063 W, 0402", Manufacturer=Vishay-Dale, Power_W=0.063, Supplier Part Number 1=541-100KJCT-ND, TempCo="200 ppm/C", Tolerance_%=5, Value1=5%, Value2=0.063W, Value_Code=100k
R107 R109: "RES, 61.9 k, 1%, 0.1 W, 0603", Manufacturer=Vishay-Dale, Power_W=0.1, Supplier Part Number 1=541-61.9KHCT-ND, TempCo="100 ppm/C", Tolerance_%=1, Value1=1%, Value2=0.1W, Value_Code=61k9, ValueDisplayed=61.9k
R108: "RES, 36.5 k, 1%, 0.1 W, 0603", Manufacturer=Vishay-Dale, Power_W=0.1, Supplier Part Number 1=541-36.5KHCT-ND, TempCo="100 ppm/C", Tolerance_%=1, Value1=1%, Value2=0.1W, Value_Code=36k5, ValueDisplayed=36.5k
R110 R115 R121: "RES, 10.0 k, 1%, 0.1 W, 0603", Manufacturer=Vishay-Dale, Power_W=0.1, Supplier Part Number 1=541-10.0KHCT-ND, TempCo="100 ppm/C", Tolerance_%=1, Value1=1%, Value2=0.1W, Value_Code=10k0, ValueDisplayed=10.0k
R111: "RES, 15.4 k, 1%, 0.1 W, 0603", Manufacturer=Vishay-Dale, Power_W=0.1, Supplier Part Number 1=541-15.4KHCT-ND, TempCo="100 ppm/C", Tolerance_%=1, Value1=1%, Value2=0.1W, Value_Code=15k4, ValueDisplayed=15.4k
R112: "RES, 22.0 k, 1%, 0.1 W, AEC-Q200 Grade 0, 0603", Manufacturer=Panasonic, Power_W=0.1, Supplier Part Number 1=P22.0KHCT-ND, TempCo="100 ppm/C", Tolerance_%=1, Value1=1%, Value2=0.1W, Value_Code=22k0, ValueDisplayed=22.0k
R113: library part CMP-0026823-2, "RES, 100 k, 5%, 0.063 W, 0402", Manufacturer=Vishay-Dale, Power_W=63mW, Supplier Part Number 1=541-100KJCT-ND, TempCo="200 ppm/C", Tolerance_%=5%, Value2=0.063W, Value_Code=100k
R114 R116 R117 R138: "RES, 47.0 k, 0.1%, 0.1 W, 0603", Manufacturer="Susumu Co Ltd", Power_W=0.1, Supplier Part Number 1=RG16P47.0KBCT-ND, TempCo="25 ppm/C", Value1=0.1%, Value2=0.1W, Value_Code=47k0, ValueDisplayed=47.0k
R118: "RES, 0.1, 5%, 0.125 W, 0805", Manufacturer=Panasonic, Power_W=0.125, Supplier Part Number 1=P.10BCT-ND, TempCo="250 ppm/C", Tolerance_%=5, Value1=5%, Value2=0.125W, Value_Code=R100, ValueDisplayed=0.1
R119: "RES, 37.4 k, 1%, 0.1 W, 0603", Manufacturer=Vishay-Dale, Power_W=0.1, Supplier Part Number 1=541-37.4KHCT-ND, TempCo="100 ppm/C", Tolerance_%=1, Value1=1%, Value2=0.1W, Value_Code=37k4, ValueDisplayed=37.4k
R120: "RES, 1.00 k, 1%, 0.1 W, AEC-Q200 Grade 0, 0603", Manufacturer=Panasonic, Power_W=0.1, Supplier Part Number 1=P1.00KHCT-ND, TempCo="100 ppm/C", Tolerance_%=1, Value1=1%, Value2=0.1W, Value_Code=1k00, ValueDisplayed=1.00k
R122 R127 RES1: "RES, 100 k, 0.1%, 0.1 W, 0603", Manufacturer="Susumu Co Ltd", Power_W=0.1, Supplier Part Number 1=RG16P100KBCT-ND, TempCo="25 ppm/C", Value1=0.1%, Value2=0.1W, Value_Code=100k
R123: "RES, 19.1 k, 1%, 0.1 W, 0603", Manufacturer="Yageo America", Power_W=0.1, Supplier Part Number 1=311-19.1KHRCT-ND, TempCo="200 ppm/C", Tolerance_%=1, Value1=1%, Value2=0.1W, Value_Code=19k1, ValueDisplayed=19.1k
R124: "RES, 24.3 k, 1%, 0.1 W, 0603", Manufacturer="Yageo America", Power_W=0.1, Supplier Part Number 1=311-24.3KHRCT-ND, TempCo="200 ppm/C", Tolerance_%=1, Value1=1%, Value2=0.1W, Value_Code=24k3, ValueDisplayed=24.3k
R125: "RES, 64.2 k, 0.1%, 0.1 W, 0603", Manufacturer="Yageo America", Power_W=0.1, TempCo="25 ppm/C", Value1=0.1%, Value2=0.1W, Value_Code=64k2, ValueDisplayed=64.2k
R126 R129 R131 R155 R169: "RES, 10.0 k, 1%, 0.1 W, 0603", Manufacturer=Panasonic, Power_W=0.1, Supplier Part Number 1=P10.0KHCT-ND, TempCo="100 ppm/C", Tolerance_%=1, Value1=1%, Value2=0.1W, Value_Code=10k0, ValueDisplayed=10.0k
R128: "RES, 28.7 k, 1%, 0.1 W, 0603", Manufacturer=Vishay-Dale, Power_W=0.1, Supplier Part Number 1=541-28.7KHCT-ND, TempCo="100 ppm/C", Tolerance_%=1, Value1=1%, Value2=0.1W, Value_Code=28k7, ValueDisplayed=28.7k
R130 R139 R141: "RES, 47.0 k, 1%, 0.1 W, 0603", Manufacturer="Yageo America", Power_W=0.1, Supplier Part Number 1=311-47.0KHRCT-ND, TempCo="200 ppm/C", Tolerance_%=1, Value1=1%, Value2=0.1W, Value_Code=47k0, ValueDisplayed=47.0k
R132 R133 R134 R140 R142: "RES, 2.0 k, 5%, 0.1 W, 0603", Manufacturer=Vishay-Dale, Power_W=0.1, Supplier Part Number 1=541-2.0KGCT-ND, TempCo="200 ppm/C", Tolerance_%=5, Value1=5%, Value2=0.1W, Value_Code=2k00, ValueDisplayed=2.0k
R135 R136 R188 R189: "RES, 300, 5%, 0.1 W, 0603", Manufacturer=Vishay-Dale, Power_W=0.1, Supplier Part Number 1=541-300GCT-ND, TempCo="200 ppm/C", Tolerance_%=5, Value1=5%, Value2=0.1W, Value_Code=300R, ValueDisplayed=300
R137 R190: "RES, 0, 1%, 0.1 W, AEC-Q200 Grade 0, 0603", Manufacturer="Stackpole Electronics Inc", Power_W=0.1, Supplier Part Number 1=RMCF0603ZT0R00CT-ND, TempCo=ppm/C, Tolerance_%=1, Value1=1%, Value2=0.1W, Value_Code=0
R146 R147 R148 R149 R150: "RES, 4.7 k, 5%, 0.1 W, 0603", Manufacturer=Bourns, Power_W=0.1, Supplier Part Number 1=CR0603-JW-472GLFCT-ND, TempCo="200 ppm/C", Tolerance_%=5, Value1=5%, Value2=0.1W, Value_Code=4k70, ValueDisplayed=4.7k
R151 R152 R153: "RES, 0, 5%, 0.1 W, 0603", Manufacturer=Vishay-Dale, Power_W=0.1, Supplier Part Number 1=541-0.0GCT-ND, TempCo="200 ppm/C", Tolerance_%=5, Value1=5%, Value2=0.1W, Value_Code=0000, ValueDisplayed=0
R156: "RES, 13.7 k, 1%, 0.1 W, 0603", Manufacturer="Yageo America", Power_W=0.1, Supplier Part Number 1=311-13.7KHRCT-ND, TempCo="200 ppm/C", Tolerance_%=1, Value1=1%, Value2=0.1W, Value_Code=13k7, ValueDisplayed=13.7k
R157 R158: "RES, 100 k, 0.05%, 0.1 W, AEC-Q200 Grade 0, 0603", Manufacturer=Panasonic, Power_W=0.1, Supplier Part Number 1=P100KBECT-ND, TempCo="10 ppm/C", Tolerance_%=0.05, Value1=0.05%, Value2=0.1W, Value_Code=100k
R160 R162 R163 R164: "RES, 10.0k ohm, 1%, 0.063W, 0402", Manufacturer=Vishay-Dale, Power_W=0.063, Supplier Part Number 1=541-10.0KLCT-ND, TempCo="100 ppm/C", Tolerance_%=1, Value1=1%, Value2=0.063W, Value_Code=10k0
R161 R165: "RES, 0 ohm, 5%, 0.1W, 0603", Manufacturer=Vishay-Dale, Power_W=0.1, Supplier Part Number 1=541-0.0GCT-ND, TempCo="200 ppm/C", Tolerance_%=5, Value1=5%, Value2=0.1W, Value_Code=0000
R166 R167 R170 R176 R177 R179 R180 R181 R182 R187: "RES, 0, 5%, 0.125 W, 0805", Manufacturer=Vishay-Dale, Power_W=0.125, Supplier Part Number 1=541-0.0ACT-ND, TempCo="200 ppm/C", Tolerance_%=5, Value1=5%, Value2=0.125W, Value_Code=0000, ValueDisplayed=0
R168: "RES, 30.9 k, 1%, 0.1 W, 0603", Manufacturer="Yageo America", Power_W=0.1, Supplier Part Number 1=311-30.9KHRCT-ND, TempCo="200 ppm/C", Tolerance_%=1, Value1=1%, Value2=0.1W, Value_Code=30k9, ValueDisplayed=30.9k
R171: library part CMP-0020616-3, "RES, 0, 5%, 0.125 W, AEC-Q200 Grade 0, 0805", Manufacturer=Panasonic, Power_W=125mW, Supplier Part Number 1=P0.0ACT-ND, TempCo="600 ppm/C", Tolerance_%=5%, Value2=0.125W, Value_Code=0000, ValueDisplayed=0
R172 R173 R174 R175: library part CMP-0023363-3, "RES, 100 k, 0.1%, 0.1 W, AEC-Q200 Grade 0, 0603", Manufacturer=Panasonic, Power_W=100mW, Supplier Part Number 1=P100KDBCT-ND, TempCo="25 ppm/C", Tolerance_%=0.1%, Value2=0.1W, Value_Code=100k
R178: "RES, 3.3 k, 5%, 0.063 W, 0402", Manufacturer=Vishay-Dale, Power_W=0.063, Supplier Part Number 1=541-3.3KJCT-ND, TempCo="200 ppm/C", Tolerance_%=5, Value1=5%, Value2=0.063W, Value_Code=3k30, ValueDisplayed=3.3k
R183 R184 R185: "RES, 976 ohm, 0.5%, 0.1W, 0603", Manufacturer="Yageo America", Power_W=0.1, TempCo="50 ppm/C", Tolerance_%=0.5, Value1=0.5%, Value2=0.1W, Value_Code=976R
R186: "RES, 10.0, 1%, 0.25 W, 0603", Manufacturer=Vishay-Dale, Power_W=0.25, Supplier Part Number 1=541-10.0SCT-ND, TempCo="100 ppm/C", Tolerance_%=1, Value1=1%, Value2=0.25W, Value_Code=10R0, ValueDisplayed=10.0
RB1: "RES, 30.1, 1%, 0.063 W, 0402", Manufacturer=Vishay-Dale, Power_W=0.063, Supplier Part Number 1=541-30.1LCT-ND, TempCo="100 ppm/C", Tolerance_%=1, Value1=1%, Value2=0.063W, Value_Code=30R1, ValueDisplayed=30.1
S1: library part CMP-0002193-2, "Switch, SPST-NO, Off-Mom, 12 V, SMD", CurrentRating_mA=50A, Manufacturer="Omron Electronic Components", Supplier Part Number 1=SW1021CT-ND
TP1 TP2 TP3 TP5 TP6 TP8 TP10 TP11 TP14 TP15 TP16 TP18 TP19 TP20 TP35 TP52 TP57 TP60 TP68 TP75 TP76 TP77 TP80 TP81 TP82 TP83 TP84 TP85 TP99 TP102 TP104 TP107 TP108 TP111: library part 5000, "Test Point, Miniature, Red, TH", Color=Red, Manufacturer=Keystone, Supplier Part Number 1=36-5000-ND
TP4 TP7 TP9 TP17 TP21 TP44 TP45 TP46 TP53 TP58 TP59 TP61 TP69 TP78 TP86 TP101 TP106: "Test Point, Miniature, Black, TH", Color=Black, Manufacturer=Keystone, Supplier Part Number 1=36-5001-ND
TP12 TP13 TP22 TP23 TP28 TP29 TP71 TP87: "Test Point, Miniature, Red, TH", Color=Red, Manufacturer=Keystone, Supplier Part Number 1=36-5000-ND
TP24 TP25 TP26 TP27 TP30 TP31 TP32 TP33 TP34 TP54 TP70 TP79 TP97 TP103 TP105: "Test Point, Miniature, Orange, TH", Color=Orange, Manufacturer=Keystone, Supplier Part Number 1=36-5003-ND
TP36 TP38 TP40 TP41 TP55 TP91 TP95 TP109: "Test Point, Miniature, Red, TH", Manufacturer=Keystone, Supplier Part Number 1=5000K-ND
TP37 TP39 TP42 TP43 TP56 TP93 TP96: "Test Point, Miniature, Black, TH", Manufacturer=Keystone, Supplier Part Number 1=5001K-ND
TP47 TP48 TP49 TP50 TP51 TP62 TP63 TP64 TP65 TP66 TP67 TP72 TP73 TP74 TP88 TP89 TP90 TP92 TP94 TP98 TP100 TP110: "Test Point, Miniature, White, TH", Color=White, Manufacturer=Keystone, Supplier Part Number 1=36-5002-ND
U1: library part CMP-0014088-2, "SIMPLE SWITCHER 4.5-V to 42-V Input, 2-A Power Module, RVQ00043A, RVQ0043A (B3QFN-43)", Alternate Manufacturer="Texas Instruments", Supplier Part Number 1=296-44384-1-ND
U2: "2A Buck Simple Switcher Nano Module, SIL0008F", Alternate Manufacturer="Texas Instruments", Alternate PartNumber=LMZ20502SILT, Supplier Part Number 1=296-44478-1-ND
U3: library part CMP-0066139-1, "SIMPLE SWITCHER(R) 2.7V to 5.5V, 1A High Density Nano Module, SIL0008F (uSIP-8)", Alternate Manufacturer="Texas Instruments", Alternate PartNumber=LMZ20501SILT, Supplier Part Number 1=296-40328-1-ND
U4: library part LM53635RNL, "C REG BUCK ADJ 3.5A SYNC 22VQFN", Alternate Manufacturer="Texas Instruments", Supplier Part Number 1=296-44791-1-ND
U5: "3-A Step-Down Converter with Hiccup Short Circuit Protection in 2x2 QFN Package, RLT0007A", Alternate Manufacturer="Texas Instruments", Alternate PartNumber=TPS62085RLTT, Supplier Part Number 1=296-40830-1-ND
U6 U9 U15: library part CMP-0013424-7, "33-V Precision Surge Protection Clamp, DRV0006A (WSON-6)", Alternate Manufacturer="Texas Instruments", Alternate PartNumber=TVS3300DRVT, Supplier Part Number 1=296-47565-1-ND
U7: library part CMP-0065929-2, "IC CONV DDR DDR2 DDR3 8SOPWRPAD", Alternate Manufacturer="Texas Instruments", Alternate PartNumber=LP2998QMR/NOPB, Supplier Part Number 1=LP2998MRX/NOPBCT-ND
U8: "Power Sequencer, 8-pin MSOP, Pb-Free", Manufacturer="Texas Instruments", PackageTopMarking=ZXTT*STBB, PowerWise=N, Supplier Part Number 1=LM3881MMTR-ND
U10: library part CMP-0065148-3, "1A Step-Down Converter With 1% Accuracy, DLC0008A (VSON-HR-8)", Alternate Manufacturer="Texas Instruments", Supplier Part Number 1=296-50127-1-ND
U11: library part CMP-0036438-3, "Single Output LDO, 3 A, 2.375 to 3.5 V Input, with DDR Termination, 10-pin SON (DRC), -40 to 85 degC, Green (RoHS & no Sb/Br)", Manufacturer="Texas Instruments", Power Good=TRUE, Rating=Catalog, Supplier Part Number 1=296-26978-1-ND
U12: library part CMP-0013868-2, "LMZM33602, RLR0018A (B2QFN-18)", Alternate Manufacturer="Texas Instruments", Supplier Part Number 1=296-48829-1-ND
U13: "3-A 17V Step-down Converter Module with Integrated Inductor, SIL0008D (uSIP-8)", Alternate Manufacturer="Texas Instruments", Alternate PartNumber=TPS82130SILT, Supplier Part Number 1=296-47436-1-ND
U14: "2A, High Efficiency Step Down Converter Module with Integrated Inductor, SIL0008C", Alternate Manufacturer="Texas Instruments", Alternate PartNumber=TPS82084SILT, Supplier Part Number 1=296-46279-1-ND
U16: library part CMP-0067005-1, "1.5A Buck Converter in SOT23 Package, DBV0005A (SOT-23-5)", Alternate Manufacturer="Texas Instruments", Alternate PartNumber=TLV62565DBVT
U17: library part CMP-0075377-4, "36-V 1-A Step-Down DC-DC Nano Module, SIL0010A (uSIP-10)", Alternate Manufacturer="Texas Instruments", Alternate PartNumber=LMZM23601V5SILT, Supplier Part Number 1=296-49462-1-ND
U18: library part CMP-0067287-1, "3A, High-Efficiency Step-Down Converter Module with Integrated Inductor, SIL0008C (uSIP-8)", Alternate Manufacturer="Texas Instruments", Alternate PartNumber=TPS82085SILT, Supplier Part Number 1=296-44401-1-ND
U19: library part CMP-0035171-2, "Dual Output LDO, 1 A, Fixed 1.8, 3.3 V Output, 2.7 to 10 V Input, 28-pin HTSSOP (PWP), -40 to 125 degC, Green (RoHS & no Sb/Br)", Manufacturer="Texas Instruments", Supplier Part Number 1=296-27080-1-ND
U20: library part CMP-0065195-3, "26-V, Low Cost, Zero-Drift, Voltage-Output, Current-Shunt Monitor With Integrated Comparator, DSG0008A (WSON-8)", Alternate Manufacturer="Texas Instruments", Supplier Part Number 1=296-49077-1-ND
U21: "1A SIMPLE SWITCHER® Nano Module with 5.5V Maximum Input Voltage, SIL0008A", Alternate Manufacturer=None, Manufacturer="Texas Instruments", Supplier Part Number 1=296-37266-1-ND
U22: library part CMP-0013453-3, "12V eFuse with Over Voltage Protection, DSG0008A (WSON-8)", Alternate Manufacturer="Texas Instruments", Alternate PartNumber=TPS259531DSGT, Supplier Part Number 1=TPS259531DSGR-ND
U23: library part CMP-0077836-1, "14-V Precision Surge Protection Clamp, DRV0006A (WSON-6)", Alternate Manufacturer="Texas Instruments", Supplier Part Number 1=TVS1400DRVR-ND
U24: library part CMP-0013542-5, "5.5-V Input, 6-A, Step-Down Converter with Integrated Inductor, MOP0024A (QFM-24)", Alternate Manufacturer="Texas Instruments", Supplier Part Number 1=296-49473-1-ND
U25: library part CMP-0076409-1, "SIMPLE SWITCHER(R) 2.95V to 6V, 4A Power Module in Small QFN package, RKG0039A (B1QFN-39)", Alternate Manufacturer="Texas Instruments", Alternate PartNumber=LMZ30604RKGT, Supplier Part Number 1=296-48323-1-ND
U26: library part CMP-0032306-1, "Processor Supervisory Circuit with Power-Fail, 2 Supply Monitored, -40 to 85 degC, 8-pin SOIC (D), Green (RoHS & no Sb/Br)", Manufacturer="Texas Instruments", Rating=Catalog, Supplier Part Number 1=296-26940-1-ND, Threshold Voltage 1 (typ)(Typ)(V)=2.93, Threshold Voltage 2 (typ)(Typ)(V)=Adjustable
U27: library part CMP-0037564-2, "Integrated Triple Supply Power Management IC for Xilinx (R) Spartan (TM)-3 FPGAs, 2.2 to 6.5 V, -40 to 85 degC, 20-pin QFN (RHL), Green (RoHS & no Sb/Br)", Manufacturer="Texas Instruments", Supplier Part Number 1=296-17835-1-ND
U28 U30: "HIGH SIDE OR-ING FET CONTROLLER", Alternate Manufacturer=-, Manufacturer="Used in BOM report", Supplier Part Number 1=LM5050MK-2/NOPBCT-ND
U29: library part CMP-0037738-2, "Buck Step Down Regulator with 2.9 to 6 V Input and 0.8 to 6 V Output, -40 to 85 degC, 8-Pin WSON (DSG), Green (RoHS & no Sb/Br)", Manufacturer="Texas Instruments", Rating=Catalog, Supplier Part Number 1=296-39442-1-ND, Switch Current Limit(Typ)(A)=2.75
U31: "Power Management IC for Li-Ion Powered Systems, RHB0032E", Alternate Manufacturer="Texas Instruments", Alternate PartNumber=TPS650250RHBT, Supplier Part Number 1=296-39462-1-ND
U32: library part CMP-0013935-4, "3.5V to 36V 5A Synchronous Step-Down Voltage Regulator, RNP0030A (WQFN-30)", Alternate Manufacturer="Texas Instruments", Alternate PartNumber=LM73605RNPRT, Supplier Part Number 1=LM73605RNPR-ND
U33: library part CMP-0032418-2, "Quad Voltage Supervisor with Manual Reset Input, DGK0008A (VSSOP-8)", Manufacturer="Texas Instruments", Rating=Catalog, Supplier Part Number 1=296-27694-1-ND, Threshold Voltage 1 (typ)(Typ)(V)=2.9, Threshold Voltage 2 (typ)(Typ)(V)=0.4
U34 U36: library part CMP-0051912-2, "Dual Buffer Gate, DRL0006A, LARGE T&R", Alternate Manufacturer="Texas Instruments", F @ Nom Voltage(Max)(Mhz)=150, Generic Part Number=SN74LVC2G34, ICC @ Nom Voltage(Max)(mA)=0.01, Operating Temperature Range(C)="-40 to 125,-40 to 85", Rating=Catalog, Supplier Part Number 1=296-18020-1-ND, tpd @ Nom Voltage(Max)(ns)=8.6,4.4,4.1,3.2, Voltage(Nom)(V)=1.8,2.5,3.3,5
U35: library part CMP-0051641-4, "Single Schmitt-Trigger Inverter, DCK0005A (SOT-SC70-5)", Alternate Manufacturer="Texas Instruments", Alternate PartNumber=SN74LVC1G14DCKT, F @ Nom Voltage(Max)(Mhz)=150, Generic Part Number=SN74LVC1G14, ICC @ Nom Voltage(Max)(mA)=0.01, Operating Temperature Range="-40 to 125 C", Rating=Catalog, tpd @ Nom Voltage(Max)(ns)=11,6.5,5.5,5, Voltage(Nom)(V)=1.8,2.5,3.3,5
U37: library part CMP-0065454-1, "36-V Low-/High-Side Bi-Directional Zero-Drift Current Sense Amp w/Precision Int Shunt Resistor, PW0016A (TSSOP-16)", Alternate Manufacturer="Texas Instruments", Alternate PartNumber=INA250A3PW, Supplier Part Number 1=296-43803-1-ND
U38: "1.4V-Capable Temperature Sensor with I2C/SMBus Interface in LM75 Form Factor & Pinout, D0008A (SOIC-8)", Alternate Manufacturer="Texas Instruments", Alternate PartNumber=TMP75BID, Supplier Part Number 1=296-40684-1-ND
U39: library part CMP-0067031-2, "IC REG BUCK ADJ 3A SYNC 14HTSSOP", Alternate Manufacturer="Texas Instruments", Alternate PartNumber=TPS54225PWP, Supplier Part Number 1=296-24557-1-ND
U40: library part CMP-0066662-2, "1.2V - 8V, 3A PFET High Side Load Switch w/ Level Shift & Adj Slew Rate Control, DDC0006A (SOT-23-T-6)", Alternate Manufacturer="Texas Instruments", Supplier Part Number 1=296-34970-1-ND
